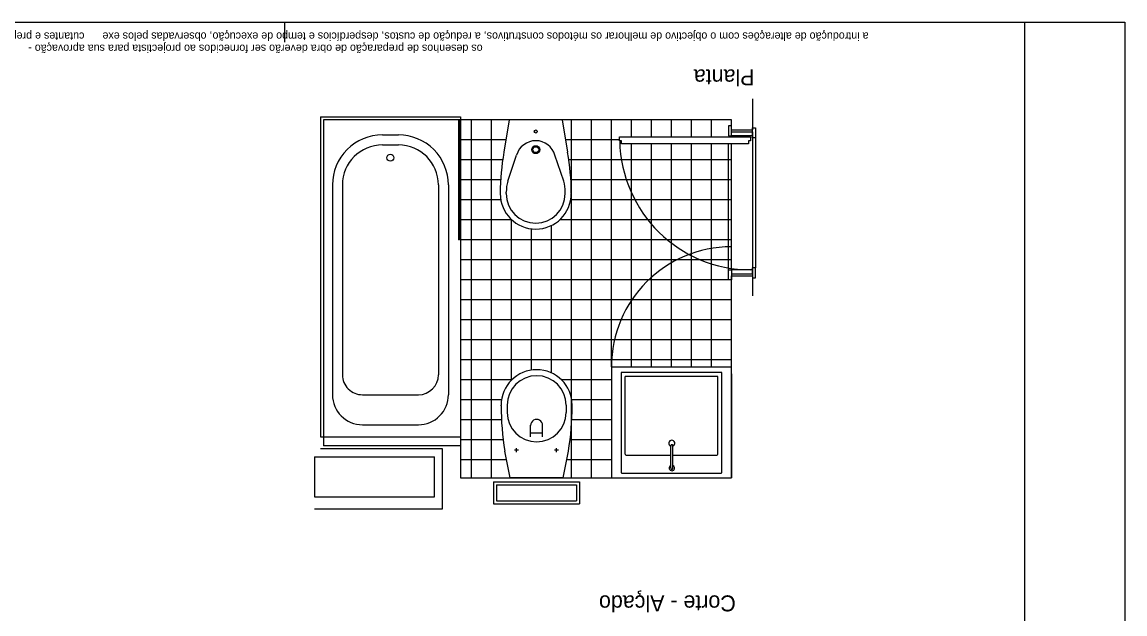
# Model space of a CAD drawing. Extents: x 1278.1 to 1289.7, y -284.6 to -278.7.
# Drawn here: x 1284.21 to 1289.72, y -281.66 to -278.7 of the extents above; entities that cross this region are included whole.
import ezdxf

# ---------------------------------------------------------------- set-up
doc = ezdxf.new("R2010")
doc.units = 0
for name, color, linetype in [('Level 1', 7, 'Continuous'), ('Level 10', 7, 'Continuous'), ('Level 11', 7, 'Continuous'), ('Level 13', 7, 'Continuous'), ('Level 2', 7, 'Continuous'), ('Level 36', 7, 'Continuous'), ('Level 4', 7, 'Continuous'), ('Level 60', 7, 'Continuous'), ('Level 62', 7, 'Continuous')]:
    doc.layers.add(name, color=color, linetype=linetype)

msp = doc.modelspace()

# ---------------------------------------------------------------- linework, layer by layer
at = {"layer": 'Level 1'}
for p, q in [((1287.8599, -279.0869), (1287.8599, -279.2419)), ((1287.7549, -279.1919), (1285.7149, -279.1919)), ((1285.7149, -279.1919), (1285.7149, -280.8219)), ((1287.7549, -279.2419), (1287.7549, -279.1919)), ((1287.7549, -279.2419), (1287.8599, -279.2419)), ((1287.7549, -280.9819), (1287.7549, -279.9719)), ((1287.7549, -279.9719), (1287.8599, -279.9719)), ((1287.8599, -279.9719), (1287.8599, -280.0719)), ((1286.3099, -280.8369), (1285.6999, -280.8369)), ((1286.3999, -280.8219), (1285.7149, -280.8219)), ((1286.3099, -281.1369), (1286.3099, -280.8369)), ((1286.3999, -280.8219), (1286.3999, -280.9819)), ((1285.6699, -280.8769), (1286.2699, -280.8769)), ((1285.6699, -280.8769), (1285.6699, -281.0769)), ((1286.2699, -281.0769), (1286.2699, -280.8769)), ((1286.3999, -280.9819), (1287.7549, -280.9819)), ((1285.6699, -281.0769), (1286.2699, -281.0769)), ((1285.6699, -281.1369), (1286.3099, -281.1369))]:
    msp.add_line(p, q, dxfattribs=at)
at = {"layer": 'Level 10'}
for p, q in [((1286.4549, -280.9819), (1286.4549, -279.1919)), ((1286.5549, -280.9819), (1286.5549, -279.1919)), ((1286.9549, -280.9819), (1286.9549, -279.1919)), ((1287.0549, -280.9819), (1287.0549, -279.1919)), ((1287.1549, -280.4269), (1287.1549, -279.1919)), ((1287.2549, -279.2769), (1287.2549, -279.1919)), ((1287.3549, -279.2769), (1287.3549, -279.1919)), ((1287.4549, -279.2769), (1287.4549, -279.1919)), ((1287.5549, -279.2769), (1287.5549, -279.1919)), ((1287.6549, -279.2769), (1287.6549, -279.1919)), ((1286.6276, -279.2919), (1286.3999, -279.2919)), ((1287.1956, -279.2919), (1286.9251, -279.2919)), ((1287.8599, -279.2819), (1287.8599, -279.9319)), ((1287.2549, -280.4269), (1287.2549, -279.3119)), ((1287.3549, -280.4269), (1287.3549, -279.3119)), ((1287.4549, -280.4269), (1287.4549, -279.3119)), ((1287.5549, -280.4269), (1287.5549, -279.3119)), ((1287.6549, -280.4269), (1287.6549, -279.3119)), ((1287.7549, -279.9419), (1287.7549, -279.3119)), ((1286.6111, -279.3919), (1286.3999, -279.3919)), ((1287.7549, -279.3919), (1286.9416, -279.3919)), ((1286.6007, -279.4919), (1286.3999, -279.4919)), ((1287.7549, -279.4919), (1286.9519, -279.4919)), ((1286.6016, -279.5919), (1286.3999, -279.5919)), ((1287.7549, -279.5919), (1286.951, -279.5919)), ((1286.6568, -279.6919), (1286.3999, -279.6919)), ((1286.6549, -280.4938), (1286.6549, -279.6902)), ((1287.7549, -279.6919), (1286.8958, -279.6919)), ((1286.7549, -280.4423), (1286.7549, -279.737)), ((1286.8549, -280.4579), (1286.8549, -279.7198)), ((1287.7549, -279.7919), (1286.3999, -279.7919)), ((1287.7549, -279.8919), (1286.3999, -279.8919)), ((1287.7549, -279.9919), (1286.3999, -279.9919)), ((1287.7549, -280.0919), (1286.3999, -280.0919)), ((1287.7549, -280.1919), (1286.3999, -280.1919)), ((1287.7549, -280.2919), (1286.3999, -280.2919)), ((1287.7549, -280.3919), (1286.3999, -280.3919)), ((1286.6568, -280.4919), (1286.3999, -280.4919)), ((1287.1549, -280.4919), (1286.9045, -280.4919)), ((1286.6053, -280.5919), (1286.3999, -280.5919)), ((1287.1549, -280.5919), (1286.9561, -280.5919)), ((1286.6049, -280.6919), (1286.3999, -280.6919)), ((1287.1549, -280.6919), (1286.9564, -280.6919)), ((1286.6135, -280.7919), (1286.3999, -280.7919)), ((1287.1549, -280.7919), (1286.9479, -280.7919)), ((1286.6303, -280.8919), (1286.3999, -280.8919)), ((1287.1549, -280.8919), (1286.9311, -280.8919))]:
    msp.add_line(p, q, dxfattribs=at)
at = {"layer": 'Level 11'}
for p, q in [((1285.6999, -279.1769), (1285.6999, -280.7769)), ((1285.6999, -279.1769), (1286.3999, -279.1769)), ((1286.3999, -279.1769), (1286.3999, -280.7769)), ((1286.644, -279.1919), (1286.6174, -279.354)), ((1286.9086, -279.1919), (1286.644, -279.1919)), ((1286.9086, -279.1919), (1286.9353, -279.354)), ((1286.0099, -279.2669), (1286.0899, -279.2669)), ((1286.0099, -279.3169), (1286.0899, -279.3169)), ((1286.6365, -279.4977), (1286.6802, -279.3685)), ((1286.9161, -279.4977), (1286.8725, -279.3685)), ((1285.7599, -279.5169), (1285.7599, -280.5669)), ((1285.8099, -279.5169), (1285.8099, -280.4669)), ((1286.2899, -279.5169), (1286.2899, -280.4669)), ((1286.3399, -279.5169), (1286.3399, -280.5669)), ((1286.5988, -279.5573), (1286.5988, -279.561)), ((1286.6288, -279.5607), (1286.6288, -279.5526)), ((1286.9238, -279.5607), (1286.9238, -279.5526)), ((1286.9538, -279.5573), (1286.9538, -279.561)), ((1287.2028, -280.4548), (1287.2028, -280.954)), ((1287.7071, -280.4548), (1287.2028, -280.4548)), ((1287.7071, -280.954), (1287.7071, -280.4548)), ((1287.2238, -280.8644), (1287.2238, -280.4759)), ((1287.686, -280.4759), (1287.2238, -280.4759)), ((1287.6861, -280.8644), (1287.686, -280.4759)), ((1285.91, -280.5669), (1286.1899, -280.5669)), ((1286.6032, -280.6225), (1286.6032, -280.6188)), ((1286.6332, -280.6191), (1286.6332, -280.6552)), ((1286.9282, -280.6191), (1286.9282, -280.6552)), ((1286.9582, -280.6225), (1286.9582, -280.6188)), ((1285.9099, -280.7169), (1286.1899, -280.7169)), ((1286.7507, -280.7771), (1286.7507, -280.7198)), ((1286.8107, -280.7771), (1286.8107, -280.7199)), ((1285.6999, -280.7769), (1286.3999, -280.7769)), ((1286.8107, -280.7594), (1286.7507, -280.7594)), ((1286.6484, -280.9819), (1286.6217, -280.8495)), ((1286.6907, -280.8434), (1286.6707, -280.8434)), ((1286.6807, -280.8534), (1286.6807, -280.8334)), ((1286.8907, -280.8434), (1286.8707, -280.8434)), ((1286.8807, -280.8534), (1286.8807, -280.8334)), ((1286.913, -280.9819), (1286.9397, -280.8495)), ((1287.451, -280.9332), (1287.451, -280.8237)), ((1287.4623, -280.9332), (1287.4623, -280.8237)), ((1287.2282, -280.8688), (1287.451, -280.8688)), ((1287.4623, -280.8688), (1287.6817, -280.8688)), ((1287.2071, -280.9584), (1287.7028, -280.9584)), ((1286.5657, -281.0019), (1286.5657, -281.1119)), ((1286.5657, -281.0019), (1286.9957, -281.0019)), ((1286.5807, -281.0169), (1286.9807, -281.0169)), ((1286.5807, -281.0169), (1286.5807, -281.0969)), ((1286.913, -280.9819), (1286.6484, -280.9819)), ((1286.9807, -281.0169), (1286.9807, -281.0969)), ((1286.9957, -281.0019), (1286.9957, -281.1119)), ((1286.5657, -281.1119), (1286.9957, -281.1119)), ((1286.5807, -281.0969), (1286.9807, -281.0969))]:
    msp.add_line(p, q, dxfattribs=at)
for centre, radius in [((1286.7763, -279.2499), 0.00766), ((1286.0499, -279.3813), 0.0173), ((1286.7763, -279.3408), 0.02), ((1286.7763, -279.3408), 0.0146)]:
    msp.add_circle(centre, radius, dxfattribs=at)
for centre, radius, start, end in [((1286.0099, -279.5169), 0.25, 89.9999, 179.9999), ((1286.0899, -279.5169), 0.25, 360, 90.0001), ((1286.7763, -279.3959), 0.1, 15.8047, 164.0683), ((1286.0099, -279.5169), 0.2, 90, 180), ((1286.0899, -279.5169), 0.2, 360, 90), ((1286.8288, -279.5526), 0.2, 164.0681, 179.9983), ((1286.7238, -279.5526), 0.2, 359.9994, 15.9307), ((1286.7763, -279.5607), 0.1775, 180.0001, 359.9998), ((1286.7763, -279.5607), 0.1475, 180.0001, 359.9998), ((1285.9099, -280.4669), 0.1, 180, 270.0001), ((1286.1899, -280.4669), 0.1, 270.0001, 359.9999), ((1286.7807, -280.6191), 0.1775, 0.0002, 179.9999), ((1286.7807, -280.6191), 0.1475, 0.0002, 179.9999), ((1285.9099, -280.5669), 0.15, 180, 270), ((1286.1899, -280.5669), 0.15, 269.9999, 0.0002), ((1288.0032, -280.6225), 1.4, 179.9999, 189.3345), ((1285.5582, -280.6225), 1.4, 350.6656, 0.0002), ((1286.7807, -280.6552), 0.1475, 180.0002, 359.9999), ((1286.7807, -280.72), 0.03, 359.9995, 180.0013), ((1287.4563, -280.8093), 0.015, 293.6307, 249.2833), ((1287.4566, -280.8231), 0.00566, 354.0176, 185.9962), ((1287.2282, -280.8644), 0.00438, 180, 270), ((1287.6817, -280.8644), 0.00438, 270, 0), ((1287.2071, -280.954), 0.00438, 180, 270), ((1287.4571, -280.9338), 0.0135, 116.7199, 67.3909), ((1287.4566, -280.9338), 0.00566, 174.0038, 5.9824), ((1287.7028, -280.954), 0.00438, 270, 0)]:
    msp.add_arc(centre, radius, start, end, dxfattribs=at)
for centre, major_axis, start_param, end_param in [((1287.9988, -279.5573), (-1.4, 0), 6.120269, 6.283187), ((1285.5538, -279.5573), (1.4, 0), 6.283183, 6.446102)]:
    msp.add_ellipse(centre, major_axis=major_axis, ratio=0.895428, start_param=start_param, end_param=end_param, dxfattribs=at)
at = {"layer": 'Level 13'}
for p, q in [((1287.7399, -279.2219), (1287.7399, -279.2719)), ((1287.7549, -279.2219), (1287.7399, -279.2219)), ((1287.7549, -279.2719), (1287.7549, -279.2219)), ((1287.7549, -279.2519), (1287.8599, -279.2519)), ((1287.7549, -279.2719), (1287.7549, -279.2519)), ((1287.8599, -279.2819), (1287.8599, -279.2319)), ((1287.8599, -279.2319), (1287.8749, -279.2319)), ((1287.8599, -279.2519), (1287.8599, -279.2819)), ((1287.8749, -279.2319), (1287.8749, -279.2819)), ((1287.1956, -279.2769), (1287.8506, -279.2769)), ((1287.1956, -279.2969), (1287.1956, -279.2769)), ((1287.2056, -279.2969), (1287.1959, -279.2969)), ((1287.2056, -279.3119), (1287.2056, -279.2969)), ((1287.7399, -279.2719), (1287.7549, -279.2719)), ((1287.8599, -279.2719), (1287.7549, -279.2719)), ((1287.8406, -279.2969), (1287.8406, -279.3119)), ((1287.8506, -279.2969), (1287.8406, -279.2969)), ((1287.8506, -279.2769), (1287.8506, -279.2969)), ((1287.8749, -279.2819), (1287.8599, -279.2819)), ((1287.8406, -279.3119), (1287.2056, -279.3119)), ((1287.7399, -279.9919), (1287.7399, -279.9419)), ((1287.7399, -279.9419), (1287.7549, -279.9419)), ((1287.8599, -279.9419), (1287.7549, -279.9419)), ((1287.7549, -279.9419), (1287.7549, -279.9619)), ((1287.7549, -279.9419), (1287.7549, -279.9919)), ((1287.7549, -279.9619), (1287.8599, -279.9619)), ((1287.8599, -279.9619), (1287.8599, -279.9319)), ((1287.8749, -279.9319), (1287.8599, -279.9319)), ((1287.8599, -279.9319), (1287.8599, -279.9819)), ((1287.8749, -279.9819), (1287.8749, -279.9319)), ((1287.7549, -279.9919), (1287.7399, -279.9919)), ((1287.8599, -279.9819), (1287.8749, -279.9819))]:
    msp.add_line(p, q, dxfattribs=at)
at = {"layer": 'Level 2'}
for p, q in [((1287.1549, -280.4269), (1287.1549, -280.9819)), ((1287.1549, -280.4269), (1287.7549, -280.4269)), ((1287.7549, -280.4619), (1287.7549, -280.9819)), ((1286.3999, -280.7769), (1286.3999, -280.8219))]:
    msp.add_line(p, q, dxfattribs=at)
at = {"layer": 'Level 36'}
for p, q in [((1286.3899, -279.1919), (1286.3899, -279.7919)), ((1286.3949, -279.1919), (1286.3949, -279.7919)), ((1286.3949, -279.7919), (1286.3899, -279.7919))]:
    msp.add_line(p, q, dxfattribs=at)
at = {"layer": 'Level 4'}
for p, q in [((1287.8749, -279.2819), (1287.8749, -279.9319)), ((1287.7399, -279.9419), (1287.7399, -279.3119))]:
    msp.add_line(p, q, dxfattribs=at)
msp.add_arc((1287.7549, -280.4269), 0.6, 90, 180, dxfattribs=at)
msp.add_ellipse((1287.8506, -279.2833), major_axis=(0, 0.6586), ratio=0.994276, start_param=1.591512, end_param=3.141593, dxfattribs=at)
at = {"layer": 'Level 62'}
for p, q in [((1285.5221, -278.8023), (1285.5221, -278.7023)), ((1289.2217, -284.6423), (1289.2217, -278.7023))]:
    msp.add_line(p, q, dxfattribs=at)
msp.add_lwpolyline([(1289.7217, -278.7023), (1289.7217, -284.6423), (1278.1221, -284.6423), (1278.1221, -278.7023)], close=True, dxfattribs=at)

# ---------------------------------------------------------------- texts
at = {"layer": 'Level 60'}
for s, p in [('Planta', (1287.8698, -278.9391)), ('Corte - Alçado', (1287.7763, -281.5706))]:
    msp.add_text(s, height=0.08, rotation=180, dxfattribs=at).set_placement(p)
at = {"layer": 'Level 62'}
for s, height, p in [('cutantes e preparadores da obra deverão ser sugeridas. não poderão no entanto ser implementadas sem o consentimento expresso dos responsáveis pela arquitectura', 0.0399996, (1284.52, -278.7543)), ('a introdução de alterações com o objectivo de melhorar os métodos construtivos, a redução de custos, desperdícios e tempo de execução, observadas pelos exe', 0.0399996, (1288.4398, -278.7543)), ('os desenhos de preparação de obra deverão ser fornecidos ao projectista para sua aprovação -', 0.04, (1286.5108, -278.8153))]:
    msp.add_text(s, height=height, rotation=180, dxfattribs=at).set_placement(p)

doc.saveas('drawing.dxf')
